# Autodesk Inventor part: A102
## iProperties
Shininess: 64.0
Length Units: 11272
Angle Units: 11279
Time Units: 11290
Mass Units: 11286
Length Display Precision: 3
Compacted: True
Part Number: A102
Document SubType Name: Modeling
Created: 2002-11
Designer: E. MOSS
Project: EVC
Description: BOLT, CLAMP
Authority: MS. TEACHER
Density: 0.0
Volumn: 0.0
Area: 0.0
PropertySet Name: Model Information
Control State: 0
Master: False
Checked Out: False
Author: E. MOSS
Revision Number: A
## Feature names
1. Extrusion1
2. Hole1
3. Hole2
4. Revolution1
